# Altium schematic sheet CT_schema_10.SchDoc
size 274 x 160 mm
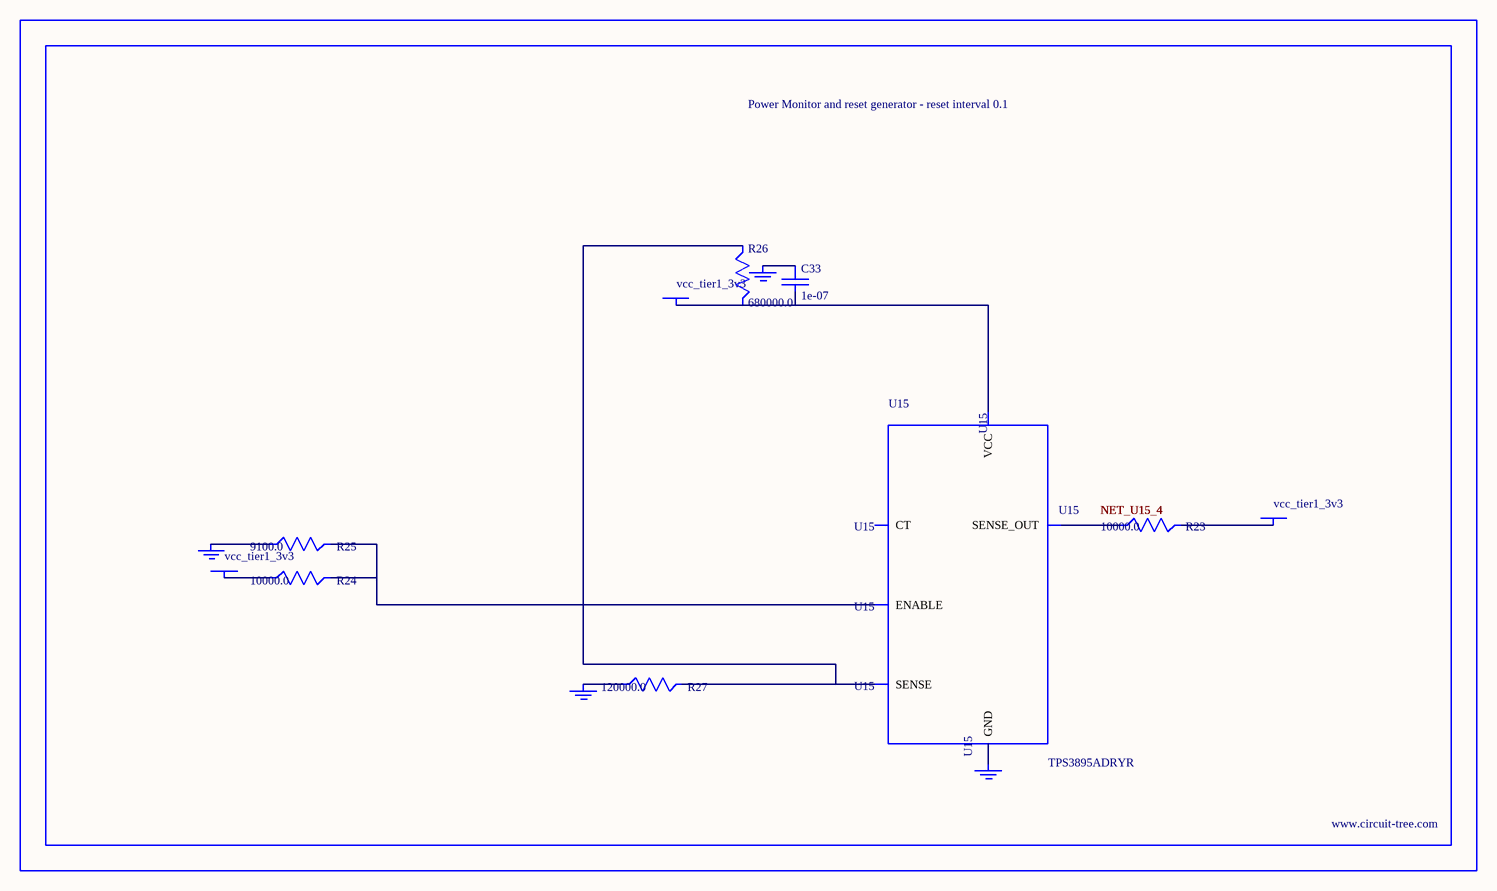
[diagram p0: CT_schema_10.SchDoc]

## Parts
BORDER9  (no value)
C33  1e-07  [C0402]
GND_INSTANCE_9_0  (no value)
GND_INSTANCE_9_1  (no value)
GND_INSTANCE_9_2  (no value)
GND_INSTANCE_9_3  (no value)
POWER_INSTANCE_9_0  vcc_tier1_3v3
POWER_INSTANCE_9_1  vcc_tier1_3v3
POWER_INSTANCE_9_2  vcc_tier1_3v3
R23  10000.0  [R0603]
R24  10000.0  [R0603]
R25  9100.0  [R0603]
R26  680000.0  [R0603]
R27  120000.0  [R0603]
U15  TPS3895ADRYR  [SON-6]

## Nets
NetC33_1: C33.1 GND_INSTANCE_9_2.0(GND)
NetC33_2: C33.2 POWER_INSTANCE_9_2.0(PWR) R26.2 U15.6(VCC)
NetGND_INSTANCE_9_0_0: GND_INSTANCE_9_0.0(GND) R25.1
NetGND_INSTANCE_9_1_0: GND_INSTANCE_9_1.0(GND) R27.1
NetGND_INSTANCE_9_3_0: GND_INSTANCE_9_3.0(GND) U15.2(GND)
NetPOWER_INSTANCE_9_0_0: POWER_INSTANCE_9_0.0(PWR) R24.1
NetPOWER_INSTANCE_9_1_0: POWER_INSTANCE_9_1.0(PWR) R23.2
NetR23_1: R23.1 U15.4(SENSE_OUT)
NetR24_2: R24.2 R25.2 U15.1(ENABLE)
NetR26_1: R26.1 R27.2 U15.3(SENSE)

Not connected (* = marked no-connect by the designer): U15 5(CT)

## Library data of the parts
BORDER9 = BORDER_PAGE9
C33 = C0402C104K3RACTU
GND_INSTANCE_9_0-GND_INSTANCE_9_3 = GND
POWER_INSTANCE_9_0-POWER_INSTANCE_9_2 = PWR
R23 R24 = RC0603JR-0710KL
R25 = RC0603JR-079K1L
R26 = RC0603JR-07680KL
R27 = RC0603JR-07120KL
